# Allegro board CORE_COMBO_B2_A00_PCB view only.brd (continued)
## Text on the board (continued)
GND3: list("[Spacing] GND3" "79.Shape to Route Keepin" "0 MIL [DEFAULT]" "0 MIL" "0.00 MIL" "DRC ERROR CLASS/GND3" "[Shape] Route Keepin/All ((-2977.43 -914.53) (7906.82 5074.84))" "[Gnd3 Shape] GNDA ((-2355.5 3645.0) (-1364.0 4696.91))" list(-1464.240000 4332.710000) nil)@@@list("kelly1_pan" "2016/03/17 14:50:04" nil "P143000035-PC" "10i-core_combo_b2.20")@@@list("jennifer_hsu" "2016/03/21 14:50:07" nil "p143000039-pc" "10i-core_combo_b2.20") | list("[Spacing] GND3" "80.Thru Pin to Thru Pin" "5 MIL [DEFAULT]" "1.04 MIL" "3.96 MIL" "DRC ERROR CLASS/GND3" "[ThruPin] Dummy (C40D40N) (-294.55 4947.5)" "[ThruPin] GND (<uTiL>cId4188<uTiL>.16) (-270.74 4868.77)" list(-284.640000 4930.130000) nil)@@@list("kelly1_pan" "2016/03/17 14:50:04" nil "P143000035-PC" "10i-core_combo_b2.20")@@@list("jennifer_hsu" "2016/03/21 14:50:08" nil "p143000039-pc" "10i-core_combo_b2.20") | list("[Spacing] GND3" "78.Thru Pin to Thru Pin" "5 MIL [DEFAULT]" "1.05 MIL" "3.95 MIL" "DRC ERROR CLASS/GND3" "[ThruPin] Dummy (C40D40N) (933.78 4947.5)" "[ThruPin] GND (<uTiL>cId4188<uTiL>.17) (909.96 4868.77)" list(923.870000 4930.130000) nil)@@@list("kelly1_pan" "2016/03/17 14:50:02" nil "P143000035-PC" "10i-core_combo_b2.20")@@@list("jennifer_hsu" "2016/03/21 14:50:05" nil "p143000039-pc" "10i-core_combo_b2.20") | list("[Spacing] GND3" "81.Shape to Route Keepin" "0 MIL [DEFAULT]" "0 MIL" "0.00 MIL" "DRC ERROR CLASS/GND3" "[Shape] Route Keepin/All ((-2977.43 -914.53) (7906.82 5074.84))" "[Gnd3 Shape] GND ((-2977.43 -914.51) (7906.82 5074.86))" list(7110.370000 -900.160000) nil)@@@list("kelly1_pan" "2016/03/17 14:50:03" nil "P143000035-PC" "10i-core_combo_b2.20")@@@list("jennifer_hsu" "2016/03/21 14:50:09" nil "p143000039-pc" "10i-core_combo_b2.20")
User.28: 36 | 24 | 12 | 1 | 10 | 20 | 30 | 16 | 11 | 6 | A48 | A1 | A16 | 7 | 32 | A32 | 25 | 48 | 8 | PJP5902 | PJP5901 | PJP5702 | 21 | 14 | H10 | H11 | PJP803 | PJP5909 | PJP10 | H5_2 | H3 | H3_2 | PJP5905 | PJP5906 | H22 | H20 | PJP5402 | PJP5403 | PJP5815 | PJP5912 | PJP5401 | JLID1 | JCSW1 | H6 | JTP1 | JDEG2 | JKB1 | H21 | H23 | PJP5501 | JDEG1 | PJP5908 | PJP5810 | JAPS1 | H24 | H12 | H8 | PJP3301 | PJP5301 | PJP5911 | PJP5703 | JFWP1 | H7 | PJP5305 | PJP5201 | PJP805 | PJP5202 | H9 | JTAG1 | H25 | SIM_B2 REV:2.0 (A00) | PCB MADE IN | JSIMUAJ2 | H1 | H2 | PJP6 | H2_2 | PJP5707 | PJP5404 | PJP5903 | PJP5904 | PJP5204 | PJP5203 | PJP5704 | PJP5307 | PJP5308 | BATTERY_B2 REV:2.0 (A00) | H7301 | H7302 | PJP5302 | PJP5701 | PJP5705 | PJP5706 | PJP7 | PJP5708 | TEL:(02)81439001 FAX:(02)28973868 | TAIPEI | www.pegatroncorp.com | DESIGNED BY PEGATRON CORPORATION | DESIGNER: | DATE: | LAY#: | 2016.03.21/17:40:41 | 10I-CORE_COMBO_B2.20 | KELLY1_PAN | TOP | CORE_B2 MAIN BOARD | REV:2.0 (A00) | 2016.03.21 | 2.0/1050mils | R&D DEPARTMENT/ENGINEER: | PROJECT DESCRIPTION: | MODEL NAME: | REV. | SILKSCREEN | PRIMARY-SIDE | CORE_COMBO_B2 | BU10/Minghong Zeng | MAIN BOARD | 2.0 | 1st | CORE_COMBO_B2 MAIN BOARD REV:2.0 (A00)
User.29: 13 | 9 | 5 | 1 | 8 | 2 | 6 | 10 | 15 | 20 | 25 | 30 | 35 | 40 | 45 | 50 | 55 | 60 | 259 | 260 | 4 | 12 | 27 | 18 | 17 | JSIMUAJ1 | JWLAN1 | H16 | JDCIN1 | JSPK1 | JEDP1 | H14 | H13 | JXDP1 | H15 | JRTC1 | JCRT1 | JFAN1 | PJP5813 | JDIMM2 | JDIMM1 | JPSEN1 | JWWAN1 | H18 | JSER1 | JGFX1 | PJP5502 | H19 | JSPI1 | JBAT1 | JDOCK1 | H17 | JUSB2 | JLAN1 | PJP5601 | PJP5603 | JHS1 | PJP5303 | PJP5304 | JIOR1 | JEPC1 | JSEC1 | PJP5812 | JODD1 | PJP5306 | PJP5811 | JRCAM1 | JBAT_PK1 | JBAT_PK2 | JUAJ1 | JSIM1 | JLED1 | JHDMI1 | HDMIU1 | JUSB1 | PJP5913 | PJP5809 | JSTRG1 | PJP5806 | JGPS1 | PJP5602 | PJP5604 | JCSW2 | JSH1 | PJP802 | TEL:(02)81439001 FAX:(02)28973868 | TAIPEI | www.pegatroncorp.com | DESIGNED BY PEGATRON CORPORATION | DESIGNER: | DATE: | LAY#: | 2016.03.21/17:40:41 | 10I-CORE_COMBO_B2.20 | KELLY1_PAN | BOT | R&D DEPARTMENT/ENGINEER: | PROJECT DESCRIPTION: | MODEL NAME: | REV. | SILKSCREEN | SECONDARY-SIDE | CORE_COMBO_B2 | BU10/Minghong Zeng | MAIN BOARD | 2.0 | 2nd
